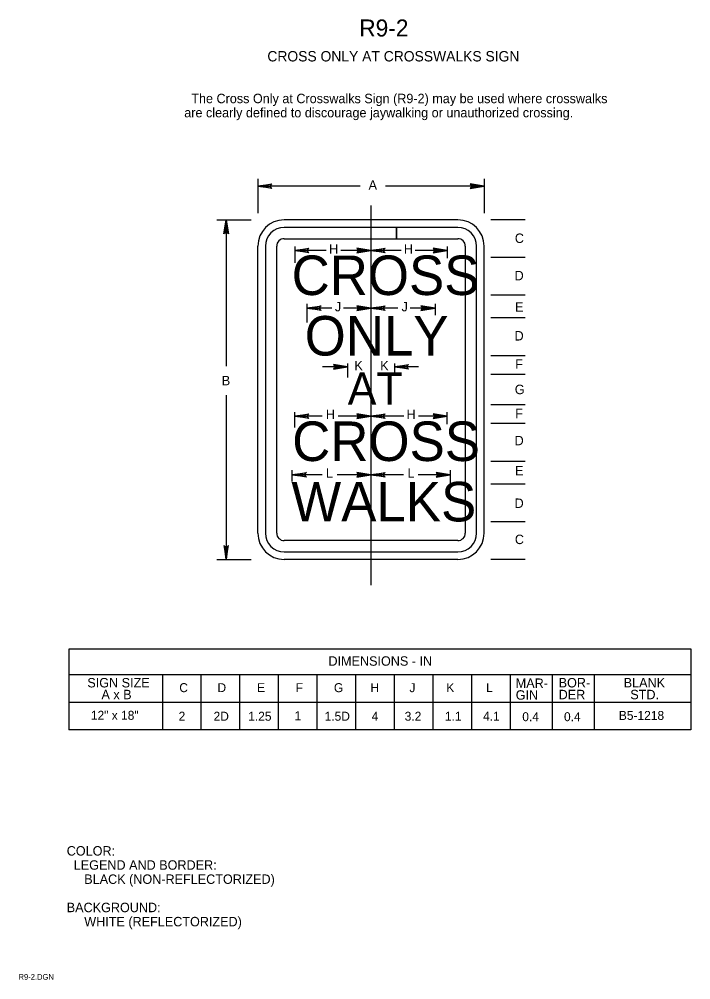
# Model space of a CAD drawing. Extents: x 0.013 to 0.191, y 0.005 to 0.259.
import ezdxf

# ---------------------------------------------------------------- set-up
doc = ezdxf.new("R2010")
doc.units = 0
for name, color, linetype in [('1', 7, 'Continuous'), ('2', 7, 'Continuous'), ('3', 7, 'Continuous')]:
    doc.layers.add(name, color=color, linetype=linetype)

# ---------------------------------------------------------------- blocks, each defined once
blk = doc.blocks.new('RARROW')
at = {"layer": '3'}
for p, q in [((-2.156, 0.285), (-2.2665, 0.384625)), ((-2.2665, 0.384625), (0, 0)), ((0, 0), (-2.2665, -0.379125)), ((-2.156, 0.285), (-2.075625, 0.12075)), ((0, 0), (-2.156, 0.285)), ((-2.14975, -0.2705), (0, 0)), ((-2.075625, 0.12075), (0, 0)), ((0, 0), (-2.074, -0.108)), ((-2.2665, -0.379125), (-2.14975, -0.2705)), ((-2.074, -0.108), (-2.14975, -0.2705))]:
    blk.add_line(p, q, dxfattribs=at)

msp = doc.modelspace()

# ---------------------------------------------------------------- linework, layer by layer
at = {"layer": '1'}
for p, q in [((0.1058, 0.20985), (0.1058, 0.10921)), ((0.11258, 0.20404), (0.0828, 0.20404)), ((0.1288, 0.20404), (0.11258, 0.20404)), ((0.11258, 0.20404), (0.11258, 0.20104)), ((0.11258, 0.20104), (0.11258, 0.20404)), ((0.0778, 0.19904), (0.0778, 0.12304)), ((0.0808, 0.12304), (0.0808, 0.19904)), ((0.0828, 0.20104), (0.11258, 0.20104)), ((0.0856, 0.19896), (0.0856, 0.19466)), ((0.11258, 0.20104), (0.1288, 0.20104)), ((0.126, 0.19896), (0.126, 0.19585)), ((0.1308, 0.19904), (0.1308, 0.12304)), ((0.1338, 0.12304), (0.1338, 0.19904)), ((0.0888, 0.18377), (0.0888, 0.17886)), ((0.1228, 0.18377), (0.1228, 0.18077)), ((0.0996, 0.16797), (0.0996, 0.16426)), ((0.112, 0.16797), (0.112, 0.1657)), ((0.0856, 0.15098), (0.0856, 0.15504)), ((0.126, 0.15193), (0.126, 0.15504)), ((0.0848, 0.13973), (0.0848, 0.13674)), ((0.1268, 0.13973), (0.1268, 0.1359)), ((0.1288, 0.12104), (0.0828, 0.12104)), ((0.0828, 0.11804), (0.1288, 0.11804))]:
    msp.add_line(p, q, dxfattribs=at)
for centre, radius, start, end in [((0.0828, 0.19904), 0.007, 90, 180), ((0.0828, 0.19904), 0.005, 90, 180), ((0.1288, 0.19904), 0.007, 0, 90), ((0.1288, 0.19904), 0.005, 0, 90), ((0.0828, 0.19904), 0.002, 90, 180), ((0.1288, 0.19904), 0.002, 0, 90), ((0.0828, 0.12304), 0.007, 180, 270), ((0.0828, 0.12304), 0.005, 180, 270), ((0.0828, 0.12304), 0.002, 180, 270), ((0.1288, 0.12304), 0.007, 270, 0), ((0.1288, 0.12304), 0.005, 270, 0), ((0.1288, 0.12304), 0.002, 270, 0)]:
    msp.add_arc(centre, radius, start, end, dxfattribs=at)
at = {"layer": '3'}
for p, q in [((0.0758, 0.21692), (0.0758, 0.20783)), ((0.1358, 0.21692), (0.1358, 0.20783)), ((0.10297, 0.21495), (0.0758, 0.21495)), ((0.1358, 0.21495), (0.10967, 0.21495)), ((0.06491, 0.20604), (0.074, 0.20604)), ((0.06742, 0.20604), (0.06742, 0.16725)), ((0.1288, 0.20604), (0.0828, 0.20604)), ((0.14668, 0.20604), (0.13759, 0.20604)), ((0.0758, 0.12304), (0.0758, 0.19904)), ((0.1358, 0.12304), (0.1358, 0.19904)), ((0.09389, 0.19795), (0.0856, 0.19795)), ((0.1058, 0.19795), (0.09784, 0.19795)), ((0.11381, 0.19795), (0.1058, 0.19795)), ((0.126, 0.19795), (0.11752, 0.19795)), ((0.14668, 0.19604), (0.13759, 0.19604)), ((0.14668, 0.18604), (0.13759, 0.18604)), ((0.09538, 0.18263), (0.0888, 0.18263)), ((0.1058, 0.18263), (0.09849, 0.18263)), ((0.11291, 0.18263), (0.1058, 0.18263)), ((0.1228, 0.18263), (0.11621, 0.18263)), ((0.14668, 0.18004), (0.13759, 0.18004)), ((0.14668, 0.17004), (0.13759, 0.17004)), ((0.0996, 0.16708), (0.09294, 0.16708)), ((0.11839, 0.16708), (0.112, 0.16708)), ((0.14668, 0.16504), (0.13759, 0.16504)), ((0.06742, 0.15959), (0.06742, 0.11604)), ((0.14668, 0.15704), (0.13759, 0.15704)), ((0.09281, 0.15403), (0.0856, 0.15403)), ((0.1058, 0.15403), (0.09706, 0.15403)), ((0.11453, 0.15403), (0.1058, 0.15403)), ((0.126, 0.15403), (0.11842, 0.15403)), ((0.14668, 0.15204), (0.13759, 0.15204)), ((0.14668, 0.14204), (0.13759, 0.14204)), ((0.09287, 0.13848), (0.08492, 0.13848)), ((0.1058, 0.13848), (0.09682, 0.13848)), ((0.11441, 0.13848), (0.1058, 0.13848)), ((0.1268, 0.13848), (0.1183, 0.13848)), ((0.14668, 0.13604), (0.13759, 0.13604)), ((0.14668, 0.12604), (0.13759, 0.12604)), ((0.06491, 0.11604), (0.074, 0.11604)), ((0.1288, 0.11604), (0.0828, 0.11604)), ((0.14668, 0.11604), (0.13759, 0.11604)), ((0.02572, 0.09239), (0.02572, 0.07089)), ((0.02576, 0.09238), (0.19059, 0.09238)), ((0.19059, 0.09238), (0.19059, 0.07089)), ((0.19059, 0.08551), (0.02572, 0.08551)), ((0.05051, 0.08551), (0.05051, 0.07089)), ((0.06072, 0.08551), (0.06072, 0.07089)), ((0.07097, 0.08551), (0.07097, 0.07089)), ((0.08122, 0.08551), (0.08122, 0.07089)), ((0.09147, 0.08551), (0.09147, 0.07089)), ((0.10172, 0.08551), (0.10172, 0.07089)), ((0.11197, 0.08551), (0.11197, 0.07089)), ((0.12222, 0.08551), (0.12222, 0.07089)), ((0.13247, 0.08551), (0.13247, 0.07089)), ((0.14267, 0.08551), (0.14267, 0.07089)), ((0.15384, 0.08551), (0.15384, 0.07089)), ((0.16497, 0.08551), (0.16497, 0.07089)), ((0.19059, 0.07814), (0.02572, 0.07814)), ((0.19059, 0.07089), (0.02572, 0.07089))]:
    msp.add_line(p, q, dxfattribs=at)

# ---------------------------------------------------------------- block references
at = {"layer": '3', "xscale": 0.001654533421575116}
for p, yscale, rotation in [((0.0758, 0.21495), 0.0016366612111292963, 180), ((0.06742, 0.20604), 0.0016366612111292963, 89.99999999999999), ((0.0856, 0.19795), 0.0016366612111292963, 180), ((0.1058, 0.19795), 0.0016366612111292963, 180), ((0.0888, 0.18263), 0.0016366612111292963, 180), ((0.1058, 0.18263), 0.0016366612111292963, 180), ((0.112, 0.16708), 0.0016366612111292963, 180), ((0.0856, 0.15403), 0.0016366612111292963, 180), ((0.1058, 0.15403), 0.0016366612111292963, 180), ((0.08492, 0.13848), 0.0016366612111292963, 180), ((0.1058, 0.13848), 0.0016366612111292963, 180), ((0.06742, 0.11604), -0.0016366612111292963, -89.99999999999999)]:
    msp.add_blockref('RARROW', p, dxfattribs=dict(at, yscale=yscale, rotation=rotation))
at = {"layer": '3', "xscale": 0.001654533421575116, "yscale": -0.0016366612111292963}
for p in [(0.1358, 0.21495), (0.1058, 0.19795), (0.126, 0.19795), (0.1058, 0.18263), (0.1228, 0.18263), (0.0996, 0.16708), (0.1058, 0.15403), (0.126, 0.15403), (0.1058, 0.13848), (0.1268, 0.13848)]:
    msp.add_blockref('RARROW', p, dxfattribs=at)

# ---------------------------------------------------------------- texts
at = {"layer": '1'}
for s, height, p in [('R9-2', 0.0045, (0.10269, 0.25462)), ('CROSS ONLY AT CROSSWALKS SIGN', 0.0027503, (0.07832, 0.248)), ('CROSS', 0.010474, (0.08475, 0.18611)), ('COLOR:', 0.0025, (0.02513, 0.03759)), ('  LEGEND AND BORDER:', 0.0024998, (0.02513, 0.03384)), ('     BLACK (NON-REFLECTORIZED) ', 0.0024998, (0.02513, 0.03009)), ('BACKGROUND:', 0.0024998, (0.02513, 0.02259)), ('     WHITE (REFLECTORIZED)          ', 0.0024998, (0.02513, 0.01884)), ('R9-2.DGN', 0.0015, (0.01236, 0.0047))]:
    msp.add_text(s, height=height, dxfattribs=at).set_placement(p)
for s, height, p in [('ONLY', 0.010474, (0.08822, 0.17008)), ('AT', 0.008531, (0.09962, 0.15706)), ('CROSS', 0.010474, (0.0849, 0.14213)), ('WALKS', 0.010474, (0.08468, 0.12613))]:
    msp.add_text(s, height=height, rotation=360, dxfattribs=at).set_placement(p)
at = {"layer": '2'}
for s, p in [('  The Cross Only at Crosswalks Sign (R9-2) may be used where crosswalks', (0.05629, 0.23694)), ('are clearly defined to discourage jaywalking or unauthorized crossing.', (0.05629, 0.23319))]:
    msp.add_text(s, height=0.0024998, dxfattribs=at).set_placement(p)
at = {"layer": '3'}
for s, height, p in [('A', 0.0025, (0.10516, 0.21403)), ('C', 0.0025, (0.14394, 0.19991)), ('H', 0.0025, (0.11452, 0.19704)), ('J', 0.0025, (0.11389, 0.18178)), ('K', 0.0025, (0.10825, 0.16614)), ('B', 0.0025, (0.06624, 0.16219)), ('H', 0.0025, (0.11523, 0.15324)), ('L', 0.0025, (0.11548, 0.13768)), ('SIGN SIZE', 0.0025, (0.03059, 0.08214)), ('MAR-', 0.0025, (0.14417, 0.08201)), ('BOR-', 0.0025, (0.15555, 0.08214)), ('BLANK', 0.0025, (0.1728, 0.08214)), ('A x B', 0.0025, (0.03434, 0.07901)), ('C', 0.00238, (0.05497, 0.08089)), ('D', 0.00238, (0.06509, 0.08089)), ('E', 0.00238, (0.07559, 0.08089)), ('F', 0.00238, (0.08584, 0.08089)), ('G', 0.00238, (0.09597, 0.08089)), ('J', 0.00238, (0.11598, 0.08089)), ('L', 0.00238, (0.13631, 0.08089)), ('DER', 0.0025, (0.15555, 0.07901)), ('STD.', 0.0025, (0.17455, 0.07901)), ('GIN', 0.0025, (0.14417, 0.07889)), ('12" x 18"', 0.002375, (0.03152, 0.07357)), ('2', 0.00238, (0.05479, 0.07332)), ('2D', 0.002375, (0.06406, 0.07332)), ('1.25', 0.002375, (0.07324, 0.07332)), ('1', 0.00238, (0.08552, 0.07343)), ('1.5D', 0.002375, (0.0935, 0.07332)), ('3.2', 0.002375, (0.11473, 0.07332)), ('4.1', 0.002375, (0.13551, 0.07332)), ('0.4', 0.002375, (0.14591, 0.0732)), ('B5-1218', 0.002375, (0.17151, 0.07353))]:
    msp.add_text(s, height=height, dxfattribs=at).set_placement(p)
for s, height, p in [('H', 0.0025, (0.09469, 0.19704)), ('D', 0.0025, (0.14387, 0.19001)), ('J', 0.0025, (0.09622, 0.18178)), ('E', 0.0025, (0.144, 0.18172)), ('D', 0.0025, (0.14387, 0.17406)), ('K', 0.0025, (0.10141, 0.16617)), ('F', 0.0025, (0.14403, 0.16656)), ('G', 0.0025, (0.14392, 0.15985)), ('H', 0.0025, (0.09385, 0.15324)), ('F', 0.0025, (0.14403, 0.15348)), ('D', 0.0025, (0.14387, 0.1463)), ('L', 0.0025, (0.09385, 0.13768)), ('E', 0.0025, (0.144, 0.13831)), ('D', 0.0025, (0.14387, 0.1297)), ('C', 0.0025, (0.14394, 0.12012)), ('DIMENSIONS - IN', 0.0024998, (0.09452, 0.08789)), ('H', 0.00238, (0.10566, 0.08089)), ('K', 0.00238, (0.12579, 0.08089)), ('4', 0.00238, (0.10597, 0.07332)), ('1.1', 0.002375, (0.12538, 0.07332)), ('0.4', 0.002375, (0.15697, 0.0732))]:
    msp.add_text(s, height=height, rotation=360, dxfattribs=at).set_placement(p)

doc.saveas('drawing.dxf')
